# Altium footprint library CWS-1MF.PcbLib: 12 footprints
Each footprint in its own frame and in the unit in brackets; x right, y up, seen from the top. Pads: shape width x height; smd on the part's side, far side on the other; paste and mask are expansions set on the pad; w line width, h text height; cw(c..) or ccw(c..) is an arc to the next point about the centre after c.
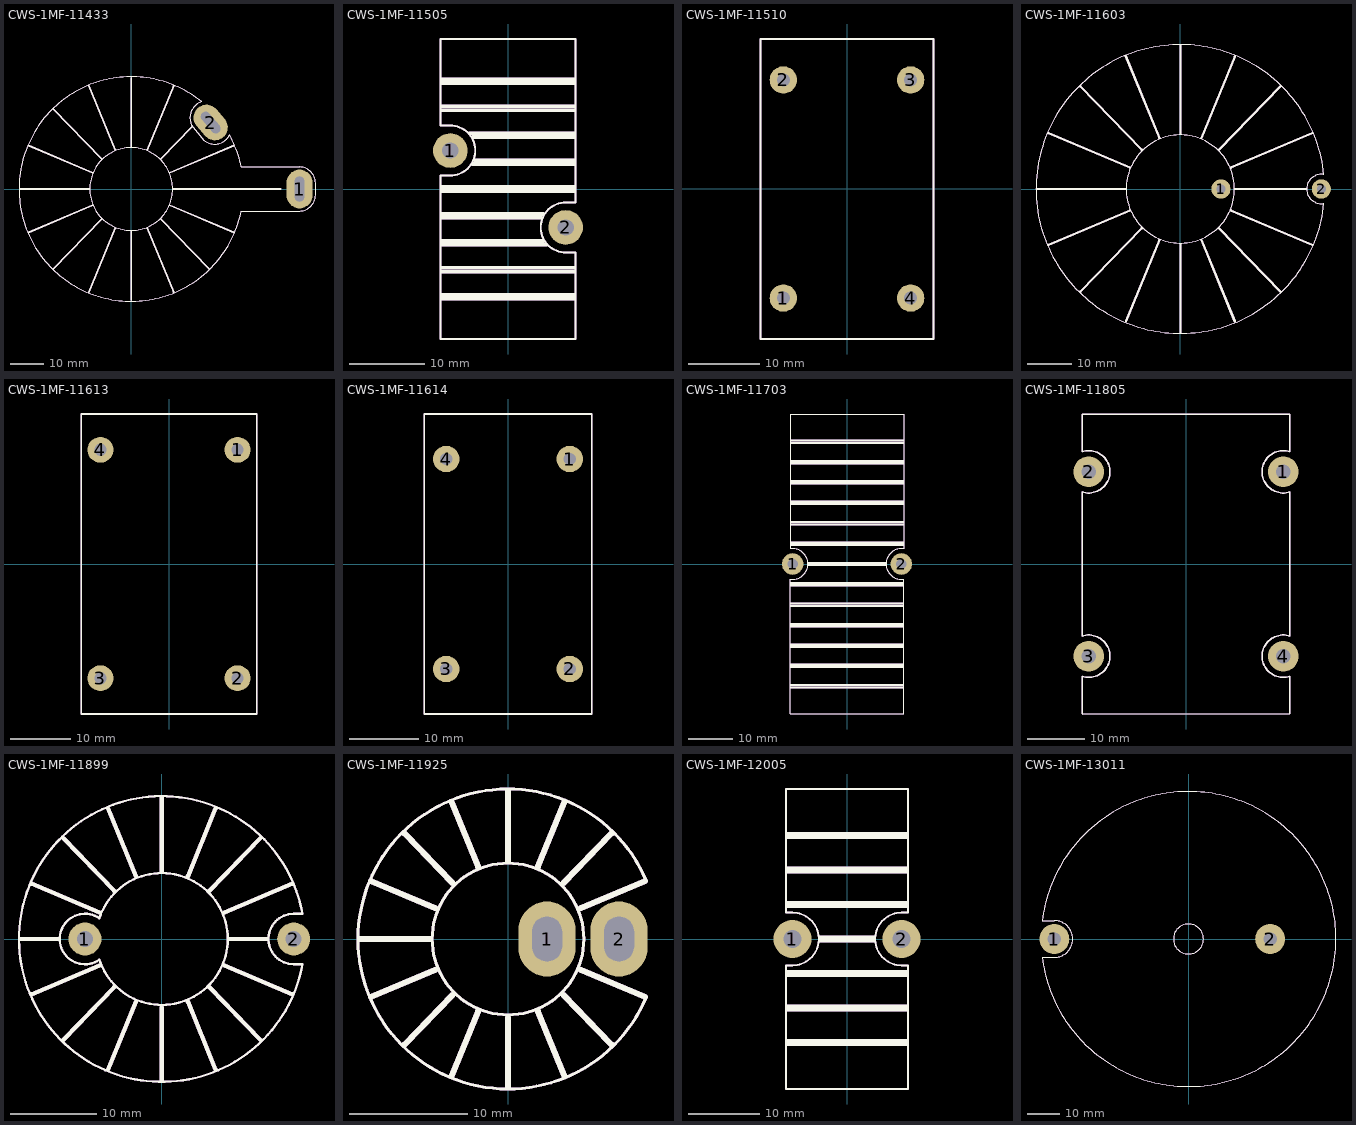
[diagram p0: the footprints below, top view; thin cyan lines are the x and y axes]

## CWS-1MF-11433 [mil]
pads (2):
  oval 300x450 hole 110 slot 290 at 90 deg: 1(1950,0)
  oval 300x450 hole 110 slot 290 at 130 deg rot 40: 2(920,770)
Top Overlay:
  circle w10: c0,0 r480
  lines w10: 1274.17,-255 1950,-255 ccw(c1950,-70) 2135,-70 2135,70 ccw(c1950,70) 1950,255 1274.71,255 ; 1274.72,-255.11 cw(c0,0) -1289.9,-161.7 cw(c0,0) 817.02,1011.18 ccw(c875,825) 696.81,745.8 842.67,563.14 ccw(c965,715) 1138.91,626.8 cw(c0,0) 1274.71,255.19
  lines w19.68: -1290,0 -485,0 ; -1190.27,504.35 -446.16,189.05 ; -1188.48,-503.59 -446.16,-189.05 ; -902.76,-927.02 -341.73,-348.32 ; -902.76,927.02 -341.73,348.32 ; -492.53,-1198.96 -186.21,-451.55 ; -492.53,1198.96 -186.21,451.55 ; 0,-1290 0,-490 ; 0,490 0,1290 ; 186.21,-451.55 490.46,-1193.91 ; 186.21,451.55 490.46,1193.91 ; 341.73,-348.32 902.91,-927.18 ; 341.73,348.32 705.91,723.97 ; 446.16,-189.05 1188.48,-503.59 ; 446.16,189.05 1188.48,503.59 ; 485,0 1730,0
Mechanical 29:
  circle w10: c0,0 r480
  lines w10: 1274.17,-255 1950,-255 ccw(c1950,-70) 2135,-70 2135,70 ccw(c1950,70) 1950,255 1274.71,255 ; 1274.72,-255.11 cw(c0,0) -1289.9,-161.7 cw(c0,0) 817.02,1011.18 ccw(c875,825) 696.81,745.8 842.67,563.14 ccw(c965,715) 1138.91,626.8 cw(c0,0) 1274.71,255.19
  lines w19.68: -1290,0 -485,0 ; -1190.27,504.35 -446.16,189.05 ; -1188.48,-503.59 -446.16,-189.05 ; -902.76,-927.02 -341.73,-348.32 ; -902.76,927.02 -341.73,348.32 ; -492.53,-1198.96 -186.21,-451.55 ; -492.53,1198.96 -186.21,451.55 ; 0,-1290 0,-490 ; 0,490 0,1290 ; 186.21,-451.55 490.46,-1193.91 ; 186.21,451.55 490.46,1193.91 ; 341.73,-348.32 902.91,-927.18 ; 341.73,348.32 705.91,723.97 ; 446.16,-189.05 1188.48,-503.59 ; 446.16,189.05 1188.48,503.59 ; 485,0 1730,0
  text "'.Designator'" at -700,235.17 h400

## CWS-1MF-11505 [mil]
pads (2):
  round 180 hole 85: 1(-300,200) 2(300,-200)
Top Overlay:
  lines w10: -350,-780 -350,70 -300,70 ccw(c-300,200) -300,330 -350,330 -350,780 350,780 350,-70 300,-70 ccw(c300,-200) 300,-330 350,-330 350,-780 -350,-780
  lines w19.68: -345,-570 345,-570 ; -345,-550 345,-550 ; -345,-430 345,-430 ; -345,-410 345,-410 ; -345,-290 198,-290 ; -345,-270 184,-270 ; -345,-150 173,-150 ; -345,-130 183,-130 ; -345,-10 345,-10 ; -345,10 345,10 ; -345,410 345,410 ; -345,430 345,430 ; -345,550 345,550 ; -345,570 345,570 ; -198,290 345,290 ; -184,130 345,130 ; -183,270 345,270 ; -173,150 345,150
Mechanical 29:
  lines w10: -350,-780 -350,70 -300,70 ccw(c-300,200) -300,330 -350,330 -350,780 350,780 350,-70 300,-70 ccw(c300,-200) 300,-330 350,-330 350,-780 -350,-780
  lines w19.68: -345,-570 345,-570 ; -345,-550 345,-550 ; -345,-430 345,-430 ; -345,-410 345,-410 ; -345,-290 198,-290 ; -345,-270 184,-270 ; -345,-150 173,-150 ; -345,-130 183,-130 ; -345,-10 345,-10 ; -345,10 345,10 ; -345,410 345,410 ; -345,430 345,430 ; -345,550 345,550 ; -345,570 345,570 ; -198,290 345,290 ; -184,130 345,130 ; -183,270 345,270 ; -173,150 345,150
  text "'.Designator'" at -1750,-64.83 h400

## CWS-1MF-11510 [mil]
pads (4):
  round 150 hole 71: 1(-350,-600) 2(-350,600) 3(350,600) 4(350,-600)
Top Overlay:
  lines w10: -475,-825 -475,-135 -475,825 475,825 475,-135 475,-825 -475,-825
Mechanical 29:
  lines w10: -475,-825 -475,-135 -475,825 475,825 475,-135 475,-825 -475,-825
  text "'.Designator'" at -1750,-64.83 h400

## CWS-1MF-11603 [mil]
pads (2):
  round 170 hole 80: 1(360,0) 2(1250,0)
Top Overlay:
  circle w10: c0,0 r480
  lines w10: -1270.06,-159.21 ccw(c0,0) 1273.6,-127.84 cw(c1250,0) 1273.6,127.84 ccw(c0,0) -1270.06,-159.21
  lines w19.68: -1275,0 -485,0 ; -1171.52,-496.41 -446.16,-189.05 ; -1171.52,496.41 -446.16,189.05 ; -888.07,-911.87 -341.73,-348.32 ; -888.07,911.87 -341.73,348.32 ; -484.07,1178.33 -186.21,451.55 ; -482,-1173.28 -186.21,-451.55 ; 0,-1270 0,-490 ; 0,490 0,1275 ; 186.21,-451.55 482,-1173.28 ; 186.21,451.55 483.04,1175.8 ; 341.73,-348.32 888.07,-911.87 ; 341.73,348.32 888.14,911.94 ; 446.16,-189.05 1171.52,-496.41 ; 446.16,189.05 1171.52,496.41 ; 485,0 1115,0
Mechanical 29:
  circle w10: c0,0 r480
  lines w10: -1270.06,-159.21 ccw(c0,0) 1273.6,-127.84 cw(c1250,0) 1273.6,127.84 ccw(c0,0) -1270.06,-159.21
  lines w19.68: -1275,0 -485,0 ; -1171.52,-496.41 -446.16,-189.05 ; -1171.52,496.41 -446.16,189.05 ; -888.07,-911.87 -341.73,-348.32 ; -888.07,911.87 -341.73,348.32 ; -484.07,1178.33 -186.21,451.55 ; -482,-1173.28 -186.21,-451.55 ; 0,-1270 0,-490 ; 0,490 0,1275 ; 186.21,-451.55 482,-1173.28 ; 186.21,451.55 483.04,1175.8 ; 341.73,-348.32 888.07,-911.87 ; 341.73,348.32 888.14,911.94 ; 446.16,-189.05 1171.52,-496.41 ; 446.16,189.05 1171.52,496.41 ; 485,0 1115,0
  text "'.Designator'" at -700,235.17 h400

## CWS-1MF-11613 [mil]
pads (4):
  round 170 hole 80: 1(450,750) 2(450,-750) 3(-450,-750) 4(-450,750)
Top Overlay:
  lines w10: -575,-985 -575,-135 -575,985 575,985 575,-135 575,-985 -575,-985
Mechanical 29:
  lines w10: -575,-985 -575,-135 -575,985 575,985 575,-135 575,-985 -575,-985
  text "'.Designator'" at -1750,-64.83 h400

## CWS-1MF-11614 [mil]
pads (4):
  round 150 hole 70: 1(350,595) 2(350,-595) 3(-350,-595) 4(-350,595)
Top Overlay:
  lines w10: -475,-850 -475,-135 -475,850 475,850 475,-135 475,-850 -475,-850
Mechanical 29:
  lines w10: -475,-850 -475,-135 -475,850 475,850 475,-135 475,-850 -475,-850
  text "'.Designator'" at -1750,-64.83 h400

## CWS-1MF-11703 [mil]
pads (2):
  round 190 hole 91: 1(-480,0) 2(480,0)
Top Overlay:
  lines w10: -500,-133.54 -500,-1325 500,-1325 500,-133.54 ; -500,-133.51 ccw(c-480,0) -499.78,133.54 ; -500,133.54 -500,1325 500,1325 500,133.54 ; 499.78,133.54 ccw(c480,0) 500,-133.51
  lines w19.68: -495,-1090 495,-1090 ; -495,-1070 495,-1070 ; -495,-910 495,-910 ; -495,-890 495,-890 ; -495,-730 495,-730 ; -495,-710 495,-710 ; -495,-550 495,-550 ; -495,-530 495,-530 ; -495,-370 495,-370 ; -495,-350 495,-350 ; -495,-190 495,-190 ; -495,-170 495,-170 ; -495,170 495,170 ; -495,190 495,190 ; -495,350 495,350 ; -495,370 495,370 ; -495,530 495,530 ; -495,550 495,550 ; -495,710 495,710 ; -495,730 495,730 ; -495,890 495,890 ; -495,910 495,910 ; -495,1070 495,1070 ; -495,1090 495,1090 ; -340,-10 340,-10 ; -340,10 340,10
Mechanical 29:
  lines w10: -500,-133.54 -500,-1325 500,-1325 500,-133.54 ; -500,-133.51 ccw(c-480,0) -499.78,133.54 ; -500,133.54 -500,1325 500,1325 500,133.54 ; 499.78,133.54 ccw(c480,0) 500,-133.51
  lines w19.68: -495,-1090 495,-1090 ; -495,-1070 495,-1070 ; -495,-910 495,-910 ; -495,-890 495,-890 ; -495,-730 495,-730 ; -495,-710 495,-710 ; -495,-550 495,-550 ; -495,-530 495,-530 ; -495,-370 495,-370 ; -495,-350 495,-350 ; -495,-190 495,-190 ; -495,-170 495,-170 ; -495,170 495,170 ; -495,190 495,190 ; -495,350 495,350 ; -495,370 495,370 ; -495,530 495,530 ; -495,550 495,550 ; -495,710 495,710 ; -495,730 495,730 ; -495,890 495,890 ; -495,910 495,910 ; -495,1070 495,1070 ; -495,1090 495,1090 ; -340,-10 340,-10 ; -340,10 340,10
  text "'.Designator'" at -1750,-64.83 h400

## CWS-1MF-11805 [mil]
pads (4):
  round 210 hole 100: 1(665,630) 2(-665,630) 3(-665,-630) 4(665,-630)
Top Overlay:
  lines w10: 710,767.84 ccw(c665,630) 710,492.16 710,-492.16 ccw(c665,-630) 710,-767.84 710,-1025 -710,-1025 -710,-767.84 ccw(c-665,-630) -710,-492.16 -710,492.16 ccw(c-665,630) -710,767.84 -710,1025 710,1025 710,768
Mechanical 29:
  lines w10: 710,767.84 ccw(c665,630) 710,492.16 710,-492.16 ccw(c665,-630) 710,-767.84 710,-1025 -710,-1025 -710,-767.84 ccw(c-665,-630) -710,-492.16 -710,492.16 ccw(c-665,630) -710,767.84 -710,1025 710,1025 710,768
  text "'.Designator'" at -1750,-64.83 h400

## CWS-1MF-11899 [mil]
pads (2):
  round 150 hole 73: 1(-350,0) 2(600,0)
Top Overlay:
  lines w10: -285.06,-94.91 cw(c-350,0) -284.85,94.76 ; -284.64,-94.77 ccw(c0,0) -284.66,94.7 ; -639.75,-115 ccw(c0,0) 639.75,-115 600,-115 cw(c600,0) 600,115 639.77,114.84 ccw(c0,0) -639.75,-115
  lines w19.68: -645,0 -470,0 ; -594.25,-251.8 -284.73,-120.65 ; -594.25,251.8 -284.73,120.65 ; -449.21,-459.18 -216.03,-218.66 ; -449.21,459.18 -216.03,218.66 ; -245,-595.01 -117.96,-285.03 ; -245,595.01 -117.96,285.03 ; 0,-645 0,-310 ; 0,305 0,645 ; 117.96,-285.03 245,-595.01 ; 117.96,285.03 245,595.01 ; 216.03,-218.66 449.21,-459.18 ; 216.03,218.66 449.21,459.18 ; 284.73,-120.65 594.25,-251.8 ; 284.73,120.65 594.25,251.8 ; 305,0 480,0
Mechanical 29:
  lines w10: -285.06,-94.91 cw(c-350,0) -284.85,94.76 ; -284.64,-94.77 ccw(c0,0) -284.66,94.7 ; -639.75,-115 ccw(c0,0) 639.75,-115 600,-115 cw(c600,0) 600,115 639.77,114.84 ccw(c0,0) -639.75,-115
  lines w19.68: -645,0 -470,0 ; -594.25,-251.8 -284.73,-120.65 ; -594.25,251.8 -284.73,120.65 ; -449.21,-459.18 -216.03,-218.66 ; -449.21,459.18 -216.03,218.66 ; -245,-595.01 -117.96,-285.03 ; -245,595.01 -117.96,285.03 ; 0,-645 0,-310 ; 0,305 0,645 ; 117.96,-285.03 245,-595.01 ; 117.96,285.03 245,595.01 ; 216.03,-218.66 449.21,-459.18 ; 216.03,218.66 449.21,459.18 ; 284.73,-120.65 594.25,-251.8 ; 284.73,120.65 594.25,251.8 ; 305,0 480,0
  text "'.Designator'" at -290,145.17 h400

## CWS-1MF-11925 [mil]
pads (2):
  oval 190x250 hole 150 slot 100 at 0 deg: 1(130,0) 2(370,0)
Top Overlay:
  circle w10: c0,0 r253
  lines w10: 460.38,-195.07 cw(c0,0) -484.91,-121.93 cw(c0,0) 460.38,195.07
  lines w19.68: -495,0 -260,0 ; -456.13,-193.28 -241.6,-102.37 ; -456.13,193.28 -241.6,102.37 ; -344.8,-351.48 -184.17,-185.8 ; -344.8,351.48 -184.17,185.8 ; -188.12,-456.21 -99.76,-240.62 ; -188.12,456.21 -99.76,240.62 ; 0,-495 0,-262 ; 0,260 0,493 ; 99.76,-240.62 188.12,-456.21 ; 99.76,240.62 188.12,456.21 ; 184.17,-185.8 344.8,-351.48 ; 184.17,185.8 344.8,351.48 ; 241.6,-102.37 456.13,-193.28 ; 241.6,102.37 456.13,193.28
Mechanical 29:
  circle w10: c0,0 r253
  lines w10: 460.38,-195.07 cw(c0,0) -484.91,-121.93 cw(c0,0) 460.38,195.07
  lines w19.68: -495,0 -260,0 ; -456.13,-193.28 -241.6,-102.37 ; -456.13,193.28 -241.6,102.37 ; -344.8,-351.48 -184.17,-185.8 ; -344.8,351.48 -184.17,185.8 ; -188.12,-456.21 -99.76,-240.62 ; -188.12,456.21 -99.76,240.62 ; 0,-495 0,-262 ; 0,260 0,493 ; 99.76,-240.62 188.12,-456.21 ; 99.76,240.62 188.12,456.21 ; 184.17,-185.8 344.8,-351.48 ; 184.17,185.8 344.8,351.48 ; 241.6,-102.37 456.13,-193.28 ; 241.6,102.37 456.13,193.28
  text "'.Designator'" at -290,145.17 h400

## CWS-1MF-12005 [mil]
pads (2):
  round 210 hole 100: 1(-300,0) 2(300,0)
Top Overlay:
  lines w10: -335,-825 -335,-145 -300,-145 ccw(c-300,0) -300,145 -335,145 -335,825 335,825 335,145 300,145 ccw(c300,0) 300,-145 335,-145 335,-825 -335,-825
  lines w19.68: -330,-580 330,-580 ; -330,-560 330,-560 ; -330,-390 330,-390 ; -330,-370 330,-370 ; -330,-200 330,-200 ; -330,-180 330,-180 ; -330,180 330,180 ; -330,200 330,200 ; -330,370 330,370 ; -330,390 330,390 ; -330,560 330,560 ; -330,580 330,580 ; -150,-10 150,-10 ; -150,10 150,10
Mechanical 29:
  lines w10: -335,-825 -335,-145 -300,-145 ccw(c-300,0) -300,145 -335,145 -335,825 335,825 335,145 300,145 ccw(c300,0) 300,-145 335,-145 335,-825 -335,-825
  lines w19.68: -330,-580 330,-580 ; -330,-560 330,-560 ; -330,-390 330,-390 ; -330,-370 330,-370 ; -330,-200 330,-200 ; -330,-180 330,-180 ; -330,180 330,180 ; -330,200 330,200 ; -330,370 330,370 ; -330,390 330,390 ; -330,560 330,560 ; -330,580 330,580 ; -150,-10 150,-10 ; -150,10 150,10
  text "'.Designator'" at -1750,-64.83 h400

## CWS-1MF-13011 [mil]
pads (2):
  round 360 hole 160: 1(-1610,0) 2(980,0)
Top Overlay:
  circle w10: c0,0 r180
  lines w10: -1756.25,-220.16 ccw(c0,0) 1757.5,-210 ccw(c0,0) -1756.25,220.16 ; -1756.25,-220 -1610,-220 ccw(c-1610,0) -1610,220 -1756.25,220
Mechanical 29:
  circle w10: c0,0 r180
  lines w10: -1756.25,-220.16 ccw(c0,0) 1757.5,-210 ccw(c0,0) -1756.25,220.16 ; -1756.25,-220 -1610,-220 ccw(c-1610,0) -1610,220 -1756.25,220
  text "'.Designator'" at -290,145.17 h400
